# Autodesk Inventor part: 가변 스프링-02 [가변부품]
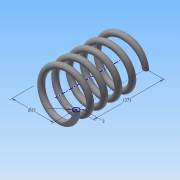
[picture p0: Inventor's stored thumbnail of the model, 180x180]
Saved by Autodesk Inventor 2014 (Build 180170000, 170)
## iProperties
Created: 2015-09
Part Number: 가변 스프링-02 [가변부품]
Material: 강철, 탄소
Document SubType Name: Modeling
Designer: study
Density: 7.87 g/cm^3
Appearance: 반연마
Mass: 18.9074 g
Surface Area: 32.5656 cm^2
Volume: 2.40246 cm^3
Author: study
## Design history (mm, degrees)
sketch "스케치1"
  geometry: L1 (0, 0)-(11, 0); L2 (11, 0)-(11, 29.043); L3 (11, 29.043)-(0, 29.043); L4 (0, 29.043)-(0, 0); C1 r 1.5 at (11, 0)
  constraints: 8 end point, 2 parallel, 1 centre point, 1 coincident, 1 horizontal, 1 perpendicular
  dimensions: "d0" = 3 diameter of C1; "d1" = 29.04259 distance between parallel lines of L3 L1 (derived); "d2" = 22 diameter of L2 L4
feature "코일1" sketch "스케치1" pitch "d3" = 10; turns "d5" = 5; dims "d4" = 29.04259 (= d1), "d6" = 0, angle "d7" = 90 deg, angle "d8" = 90 deg, "d9" = 0, "d10" = 0
node "작업 평면1"
sketch "스케치2"
  geometry: L1 (-12.5, 0)-(-9.5, 0) reference; 1 further point
  constraints: 1 horizontal alignment
extrude "돌출1" cut sketch "스케치2" stored distance "d12" = 10; taper "d13" = 0 deg
node "작업 평면2"
sketch "스케치3"
  geometry: L1 (-9.5, 0)-(-12.5, 0) reference; 1 further point
  constraints: 1 horizontal alignment
extrude "돌출2" cut sketch "스케치3" stored distance "d15" = 10; taper "d16" = 0 deg
node "솔리드1"
node "절단 모서리 투영1"
node "절단 모서리 투영2"
other parameters: "d11" = 0, "d14" = 29.04259 (= d1)
